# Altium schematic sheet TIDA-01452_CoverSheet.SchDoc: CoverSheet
size 431 x 279 mm; Date: Not shown in title block; ApprovedBy: Not shown in title block; CheckedBy: Not shown in title block; Author: Not shown in title block; CompanyName: Not shown in title block; DrawnBy: Il Han Kim; Engineer: Not shown in title block; Organization: Not shown in title block; Address1: Not shown in title block; Address2: Not shown in title block; Address3: Not shown in title block; Address4: Not shown in title block; DocumentNumber: 2; Revision: Use project parameter SCH_Rev; SheetNumber: 1; SheetTotal: 12; PageSetup: Record=PageOptions¦CenterHorizontal=True¦CenterVertical=True¦PrintScale=1.00¦XCorrection=1.00¦YCorrection=1.00¦PrintKind=0¦BorderSize=5000000¦LeftOffset=0¦BottomOffset=0¦Orientation=2¦PaperLength=1000¦PaperWidth=1000¦Scale=100¦PaperSource=15¦PrintQuality=600¦MediaType=1¦DitherType=10¦PaperKind=Letter¦PrintScaleMode=1
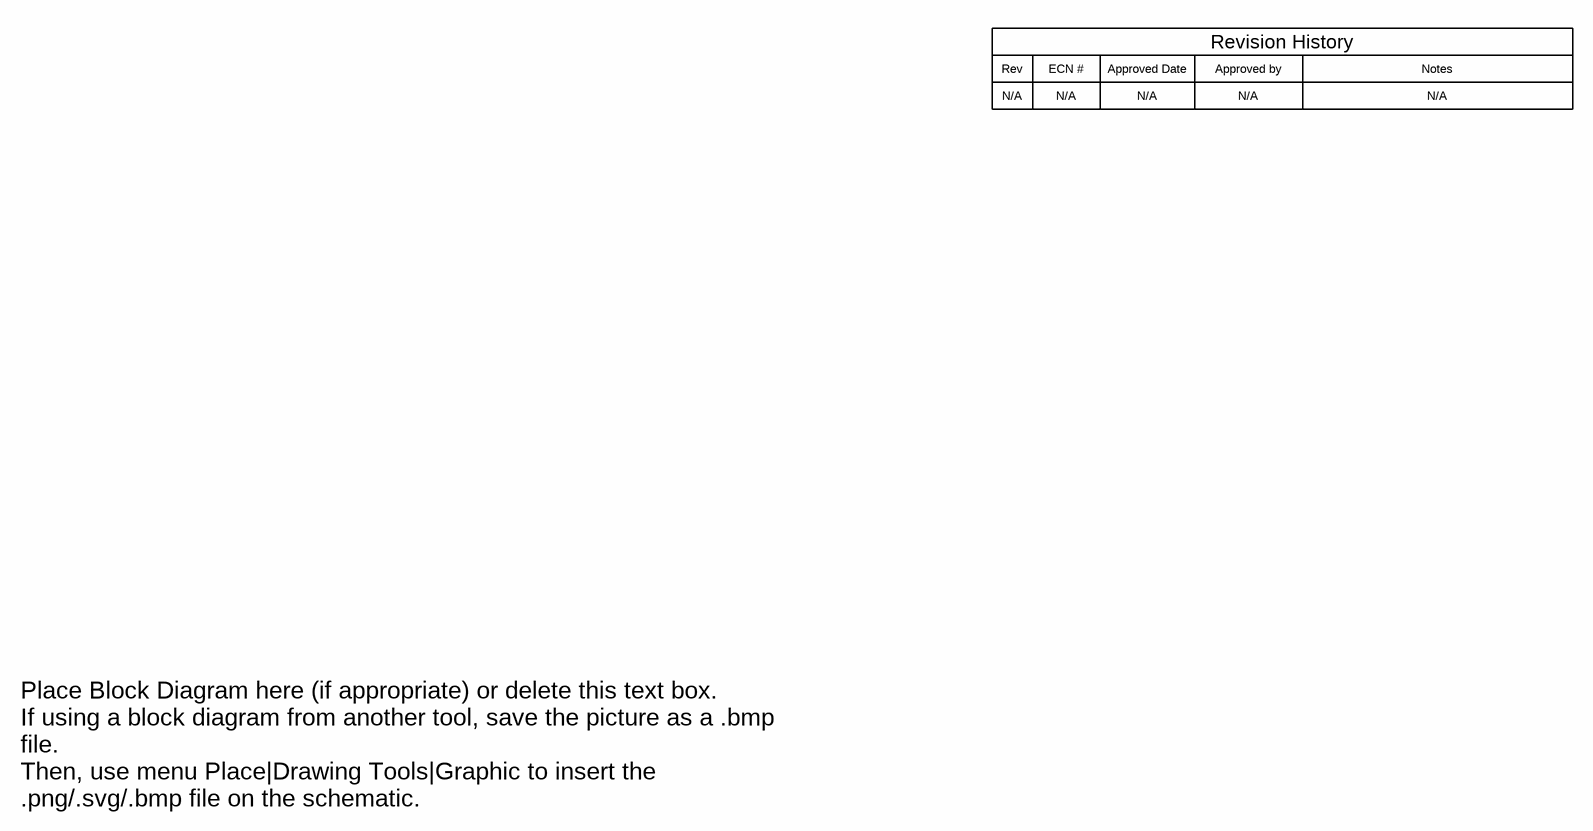
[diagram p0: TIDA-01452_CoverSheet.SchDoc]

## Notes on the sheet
- Rev
- N/A
- ECN #
- Approved Date
- Approved by
- Revision History
- Notes
- Place Block Diagram here (if appropriate) or delete this text box.
  If using a block diagram from another tool, save the picture as a .bmp file.
  Then, use menu Place|Drawing Tools|Graphic to insert the .png/.svg/.bmp file on the schematic.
